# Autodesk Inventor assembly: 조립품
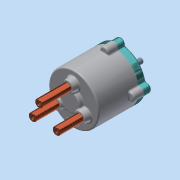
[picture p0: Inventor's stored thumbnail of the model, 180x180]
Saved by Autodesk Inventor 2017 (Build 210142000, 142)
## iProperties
Part Number: 조립품
Material: 일반
Document SubType Name: Assembly
Designer: MRC
Author: MRC
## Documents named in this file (14)
- C:\Users\MRC\Desktop\610708V1013\610708V1013\조립품.iam
- C:\Users\MRC\Desktop\610708V1013\610708V1013\본체.ipt
- C:\Users\MRC\Desktop\610708V1013\610708V1013\멈춤링 10 x 1.ipt
- C:\Users\MRC\Desktop\610708V1013\610708V1013\멈춤링 22 x 1.2.ipt
- C:\Users\MRC\Desktop\610708V1013\610708V1013\메인 축.ipt
- C:\Users\MRC\Desktop\610708V1013\610708V1013\베어링 NA 4900.ipt
- C:\Users\MRC\Desktop\610708V1013\610708V1013\볼트 M5.ipt
- C:\Users\MRC\Desktop\610708V1013\610708V1013\슬라이드 축.ipt
- C:\Users\MRC\Desktop\610708V1013\610708V1013\오일실.ipt
- C:\Users\MRC\Desktop\610708V1013\610708V1013\커버.ipt
- C:\Users\MRC\Desktop\610708V1013\610708V1013\판캠.ipt
- C:\Users\MRC\Desktop\610708V1013\610708V1013\스프링1.ipt
- C:\Users\MRC\Desktop\610708V1013\610708V1013\스프링2.ipt
- C:\Users\MRC\Desktop\610708V1013\610708V1013\스프링3.ipt
